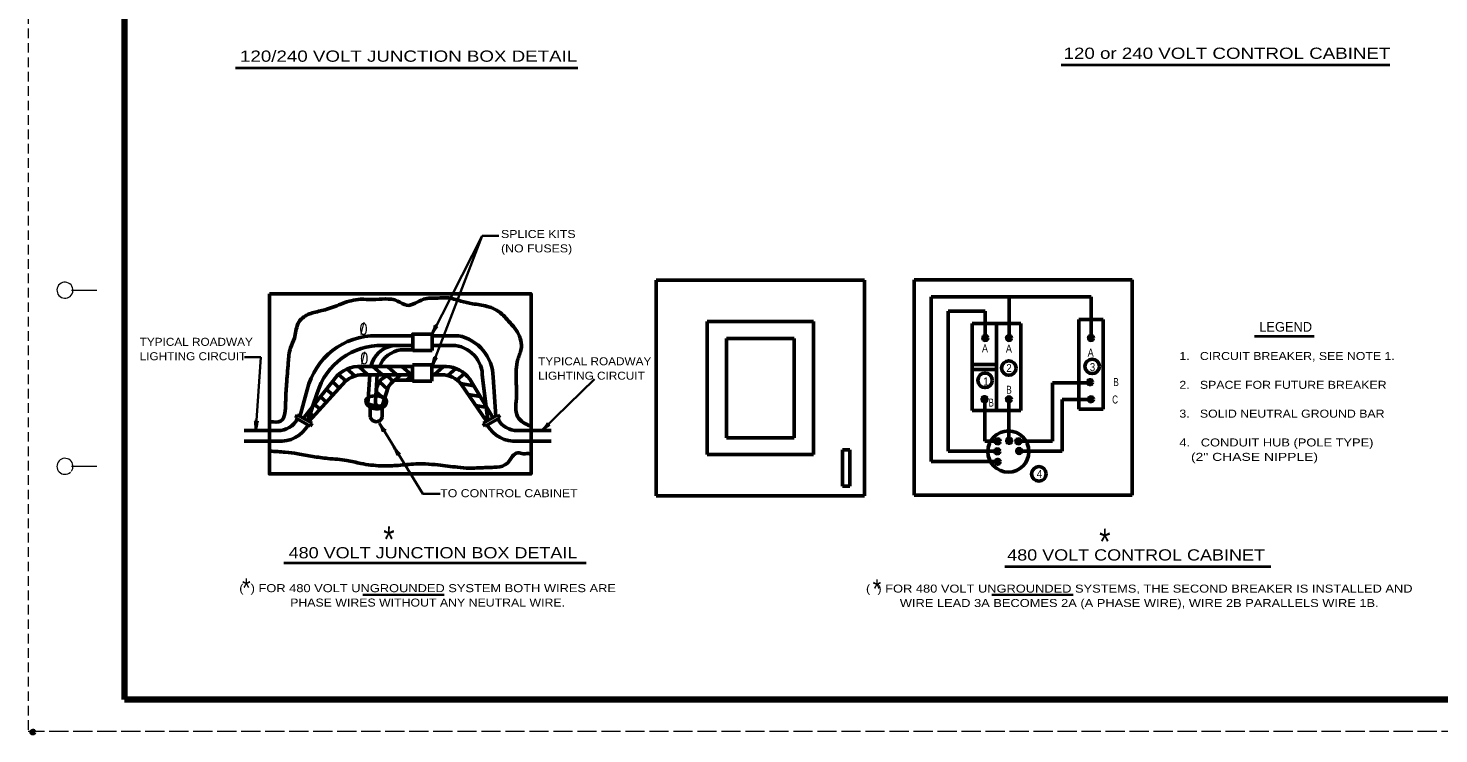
# Model space of a CAD drawing. Extents: x -1 to 679, y -1 to 440.
# Drawn here: x -1.1 to 439.6, y -1 to 219.3 of the extents above; entities that cross this region are included whole.
import ezdxf
from ezdxf.enums import TextEntityAlignment as Align

# ---------------------------------------------------------------- set-up
doc = ezdxf.new("R2010")
doc.units = 0
doc.linetypes.add('LONG_DASHED', pattern=[7.5, 6, -1.5])
doc.linetypes.add('MEDIUM_DASHED', pattern=[4.5, 3, -1.5])
doc.layers.add('1', color=7, linetype='Continuous', lineweight=53)
doc.layers.add('61', color=7, linetype='Continuous', lineweight=35)

msp = doc.modelspace()

# ---------------------------------------------------------------- hatches: boundary and pattern name
at = {"layer": '1'}
for points in [[(298.682, 122.583, 1), (297.169, 122.583, 1)], [(306.08, 122.568, 1), (304.568, 122.568, 1)], [(331.689, 122.56, 1), (330.176, 122.56, 1)], [(331.402, 108.766, 1), (329.889, 108.766, 1)], [(298.426, 103.469, 1), (296.913, 103.469, 1)], [(306.044, 103.404, 1), (304.531, 103.404, 1)], [(331.7, 103.437, 1), (330.188, 103.437, 1)], [(302.516, 90.295, 1), (301.003, 90.295, 1)], [(306.115, 90.459, 1), (304.602, 90.459, 1)], [(308.978, 90.295, 1), (307.465, 90.295, 1)], [(302.434, 87.186, 1), (300.921, 87.186, 1)], [(302.516, 83.913, 1), (301.003, 83.913, 1)], [(309.223, 87.268, 1), (307.71, 87.268, 1)], [(0.787, -0.545, 1), (-0.213, -0.545, 1)], [(0.787, -0.545, 1), (-0.213, -0.545, 1)], [(0.907, -0.519, 1), (-0.093, -0.519, 1)], [(0.909, -0.519, 1), (-0.091, -0.519, 1)], [(0.934, -0.545, 1), (-0.066, -0.545, 1)], [(0.934, -0.545, 1), (-0.066, -0.545, 1)]]:
    msp.add_hatch(color=256, dxfattribs=at).paths.add_polyline_path(points)

# ---------------------------------------------------------------- linework, layer by layer
at = {"layer": '1', "linetype": 'MEDIUM_DASHED', "lineweight": 13}
msp.add_line((-1.032, 439.694), (-1.093, -0.346), dxfattribs=at)
at = {"layer": '1', "lineweight": 40}
for p, q in [((321.613, 207.868), (424.303, 207.868)), ((63.626, 206.967), (170.602, 206.967)), ((382.012, 123.116), (400.622, 123.116)), ((78.815, 52.367), (173.2, 52.367)), ((304.007, 51.183), (387.14, 51.183))]:
    msp.add_line(p, q, dxfattribs=at)
at = {"layer": '1', "lineweight": 35}
for p, q in [((140.744, 154.494), (125.059, 123.814)), ((140.744, 154.494), (125.122, 113.85)), ((140.744, 154.494), (145.973, 154.494)), ((71.581, 116.56), (66.438, 116.564)), ((69.975, 93.743), (71.581, 116.56)), ((159.518, 93.747), (175.781, 109.732)), ((103.4, 42.355), (128.861, 42.355)), ((299.989, 42.341), (325.388, 42.341))]:
    msp.add_line(p, q, dxfattribs=at)
at = {"layer": '1'}
for p, q in [((195.111, 140.582), (195.111, 73.276)), ((195.111, 140.582), (260.149, 140.582)), ((260.149, 140.582), (260.149, 73.276)), ((275.696, 140.762), (275.696, 73.456)), ((275.696, 140.762), (343.758, 140.762)), ((343.758, 140.762), (343.758, 73.456)), ((280.989, 135.469), (280.989, 84.044)), ((280.989, 135.469), (330.935, 135.469)), ((305.31, 135.469), (305.31, 121.856)), ((330.935, 135.469), (330.935, 121.856)), ((286.283, 130.931), (286.283, 87.211)), ((286.283, 130.931), (297.894, 130.931)), ((297.894, 130.931), (297.894, 121.856)), ((327.154, 100.326), (327.154, 128.307)), ((327.154, 128.307), (334.716, 128.307)), ((334.716, 100.326), (334.716, 128.307)), ((119.059, 123.814), (125.059, 123.814)), ((119.059, 123.814), (119.059, 118.715)), ((119.059, 123.814), (119.059, 118.715)), ((119.059, 118.715), (119.059, 123.814)), ((125.059, 118.715), (125.059, 123.814)), ((210.993, 127.726), (210.993, 86.132)), ((210.993, 127.726), (244.268, 127.726)), ((244.268, 127.726), (244.268, 86.132)), ((293.846, 127.15), (293.846, 99.925)), ((293.846, 127.15), (308.971, 127.15)), ((301.408, 127.15), (301.408, 99.925)), ((308.971, 127.15), (308.971, 99.925)), ((119.059, 123.278), (107.809, 123.278)), ((109.684, 120.278), (119.059, 120.278)), ((119.059, 120.278), (109.684, 120.278)), ((125.059, 120.278), (125.059, 123.278)), ((125.059, 120.278), (131.434, 120.278)), ((217.043, 122.432), (217.043, 91.426)), ((217.043, 122.432), (238.218, 122.432)), ((238.218, 122.432), (238.218, 91.426)), ((119.268, 118.909), (115.258, 118.909)), ((119.059, 118.715), (125.059, 118.715)), ((98.163, 109.165), (95.858, 111.207)), ((100.925, 110.726), (98.467, 112.903)), ((119.059, 113.713), (101.809, 113.713)), ((105.03, 111.097), (102.064, 113.725)), ((103.309, 111.097), (119.003, 111.097)), ((103.309, 111.097), (119.003, 111.097)), ((105.04, 101.979), (105.613, 111.097)), ((109.554, 111.097), (106.601, 113.713)), ((112.956, 109.058), (111.052, 110.746)), ((114.078, 111.097), (111.125, 113.713)), ((115.356, 111.097), (113.409, 109.372)), ((118.602, 111.097), (115.649, 113.713)), ((119.074, 111.097), (117.127, 109.372)), ((119.003, 114.166), (125.003, 114.166)), ((119.003, 114.166), (119.003, 109.066)), ((125.003, 114.166), (125.003, 109.066)), ((129.559, 113.713), (125.003, 113.713)), ((128.059, 111.097), (125.003, 111.097)), ((125.686, 111.097), (128.639, 113.713)), ((129.95, 110.867), (132.456, 113.087)), ((132.859, 109.435), (135.181, 111.493)), ((140.78, 110.192), (142.49, 96.791)), ((145.019, 98.095), (144.174, 110.322)), ((293.846, 114.294), (301.408, 114.294)), ((301.408, 112.781), (293.846, 112.781)), ((86.093, 106.399), (83.75, 97.997)), ((94.094, 109.074), (84.835, 97.454)), ((98.047, 109.038), (86.553, 96.459)), ((94.115, 104.735), (92.076, 106.542)), ((96.139, 106.95), (93.948, 108.891)), ((110.188, 103.495), (107.599, 105.788)), ((111.172, 106.631), (108.62, 108.893)), ((111.358, 107.222), (109.591, 101.593)), ((113.456, 109.372), (119.003, 109.372)), ((119.003, 109.066), (125.003, 109.066)), ((138.075, 107.677), (133.981, 108.374)), ((134.116, 108.179), (142.124, 96.581)), ((136.869, 109.685), (144.072, 97.694)), ((330.643, 108.619), (318.864, 108.619)), ((318.864, 90.372), (318.864, 108.619)), ((86.282, 96.821), (89.213, 105.333)), ((90.067, 100.305), (88.332, 101.843)), ((92.091, 102.52), (90.204, 104.192)), ((108.19, 101.256), (107.345, 102.005)), ((140.112, 104.287), (136.362, 104.926)), ((142.148, 100.897), (138.744, 101.477)), ((297.76, 103.382), (297.76, 90.372)), ((305.285, 103.301), (305.285, 90.386)), ((331.052, 103.382), (321.889, 103.382)), ((321.889, 87.211), (321.889, 103.382)), ((82.97, 98.603), (82.412, 97.627)), ((82.412, 97.627), (87.01, 94.999)), ((82.97, 98.603), (87.569, 95.975)), ((82.97, 98.603), (87.569, 95.975)), ((88.043, 98.09), (86.46, 99.493)), ((105.782, 97.886), (105.782, 100.886)), ((109.532, 97.886), (109.532, 100.886)), ((141.064, 95.975), (145.663, 98.603)), ((141.064, 95.975), (145.663, 98.603)), ((146.221, 97.627), (141.622, 94.999)), ((145.663, 98.603), (146.221, 97.627)), ((308.971, 99.925), (293.846, 99.925)), ((327.154, 100.326), (334.716, 100.326)), ((76.836, 93.688), (66.336, 93.688)), ((87.569, 95.975), (87.01, 94.999)), ((141.064, 95.975), (141.622, 94.999)), ((151.796, 93.688), (162.296, 93.688)), ((76.836, 90.313), (66.336, 90.313)), ((151.796, 90.313), (162.296, 90.313)), ((217.043, 91.426), (238.218, 91.426)), ((297.76, 90.372), (301.359, 90.372)), ((308.312, 90.372), (318.864, 90.372)), ((210.993, 86.132), (244.268, 86.132)), ((253.343, 87.645), (253.343, 76.301)), ((253.343, 87.645), (255.611, 87.645)), ((255.611, 87.645), (255.611, 76.301)), ((280.989, 84.044), (301.359, 84.044)), ((286.283, 87.211), (301.359, 87.211)), ((308.312, 87.211), (321.889, 87.211)), ((253.343, 76.301), (255.611, 76.301)), ((195.111, 73.276), (260.149, 73.276)), ((275.696, 73.456), (343.758, 73.456))]:
    msp.add_line(p, q, dxfattribs=at)
msp.add_lwpolyline([(74.272, 136.366), (156.023, 136.366), (156.023, 80.116), (74.272, 80.116)], close=True, dxfattribs=at)
for points in [[(119.059, 118.715), (119.059, 123.814), (119.059, 118.715)], [(109.684, 120.278), (119.059, 120.278), (119.059, 118.715)], [(133.309, 123.278), (125.059, 123.278), (125.059, 120.278)], [(101.809, 113.713), (119.059, 113.713), (105.916, 113.713)], [(107.956, 111.097), (107.296, 101.266), (105.04, 101.979)]]:
    msp.add_lwpolyline(points, dxfattribs=at)
at = {"layer": '1', "lineweight": 35}
msp.add_lwpolyline([(108.607, 95.941), (122.181, 73.932), (127.628, 73.932)], dxfattribs=at)
at = {"layer": '1'}
for centre, radius in [((297.926, 122.583), 0.756), ((305.324, 122.568), 0.756), ((330.932, 122.56), 0.756), ((305.256, 113.19), 2.269), ((331.298, 113.712), 2.269), ((297.822, 109.345), 2.269), ((330.645, 108.766), 0.756), ((297.669, 103.469), 0.756), ((305.288, 103.404), 0.756), ((330.944, 103.437), 0.756), ((305.108, 87.11), 6.428), ((301.759, 90.295), 0.756), ((305.358, 90.459), 0.756), ((308.221, 90.295), 0.756), ((301.677, 87.186), 0.756), ((301.759, 83.913), 0.756), ((308.467, 87.268), 0.756), ((314.651, 80.125), 2.269), ((0.287, -0.545), 0.5), ((0.287, -0.545), 0.5), ((0.407, -0.519), 0.5), ((0.409, -0.519), 0.5), ((0.434, -0.545), 0.5), ((0.434, -0.545), 0.5)]:
    msp.add_circle(centre, radius, dxfattribs=at)
for centre, radius, start, end in [((107.465, 101.312), 21.969, 89.10191, 166.6119), ((109.243, 99.389), 20.894, 88.79119, 163.46999), ((114.424, 111.616), 8.762, 99.33482, 166.15506), ((131.134, 110.627), 9.655, 357.41613, 88.21923), ((130.68, 110.039), 13.497, 1.20125, 78.7649), ((116.679, 110.263), 8.762, 99.33482, 156.80988), ((102.391, 104.01), 9.72, 93.43035, 148.6064), ((103.287, 103.397), 7.7, 89.83779, 132.89463), ((112.786, 105.947), 5.102, 84.95544, 184.27235), ((128.081, 103.397), 7.7, 38.39054, 90.16221), ((128.978, 104.01), 9.72, 35.7187, 86.56965), ((115.947, 104.841), 5.17, 118.7963, 152.57809), ((77.021, 100.583), 6.897, 268.46061, 331.14947), ((107.657, 98.375), 1.938, 194.60928, 345.39072), ((151.611, 100.583), 6.897, 208.85053, 271.53939), ((77.574, 100.417), 10.131, 265.82241, 330.12509), ((151.058, 100.417), 10.131, 209.87491, 274.17759)]:
    msp.add_arc(centre, radius, start, end, dxfattribs=at)
at = {"layer": '1', "lineweight": 40}
for centre, major_axis, ratio, start_param, end_param in [((125.31, 124.911), (-0.674, -1.661), 0.122415, 0.8963533, 3.1415927), ((125.758, 124.715), (-0.956, -1.484), 0.07063, 3.1407148, 5.41811), ((125.255, 114.968), (-0.495, -1.723), 0.122415, 0.8963533, 3.1415927), ((125.721, 114.82), (0.794, 1.576), 0.07063, 6.2823074, 8.5597026), ((69.776, 94.851), (0.03, -1.792), 0.122415, 0.8963533, 3.1415927), ((70.265, 94.846), (0.299, 1.74), 0.07063, 6.2823074, 8.5597026), ((109.015, 94.877), (0.772, -1.587), 0.07063, 6.2823074, 8.5597026), ((109.015, 94.877), (0.772, -1.587), 0.07063, 6.2823074, 8.5597026), ((109.415, 95.158), (-1.07, 1.438), 0.122415, 0.8963533, 3.1415927), ((109.415, 95.158), (-1.07, 1.438), 0.122415, 0.8963533, 3.1415927), ((160.103, 94.709), (-1.164, -1.363), 0.122415, 0.8963533, 3.1415927), ((160.466, 94.382), (1.376, 1.106), 0.07063, 6.2823074, 8.5597026), ((113.583, 87.47), (0.772, -1.587), 0.07063, 6.2823074, 8.5597026), ((113.983, 87.752), (-1.07, 1.438), 0.122415, 0.8963533, 3.1415927)]:
    msp.add_ellipse(centre, major_axis=major_axis, ratio=ratio, start_param=start_param, end_param=end_param, dxfattribs=at)
at = {"layer": '1'}
msp.add_ellipse((107.635, 102.881), major_axis=(3.232, -0.12), ratio=0.757256, start_param=3.1415927, end_param=6.2831853, dxfattribs=at)
msp.add_ellipse((107.635, 102.881), major_axis=(3.232, -0.12), ratio=0.505045, dxfattribs=at)
for points in [[(74.545, 96.436), (77.76, 96.62), (79.321, 102.409), (79.597, 108.106), (80.148, 114.905), (80.883, 119.5), (82.077, 122.532), (83.179, 126.943), (84.649, 128.872), (88.139, 130.526), (92.181, 131.537), (97.141, 133.375), (99.805, 134.202), (102.745, 134.661), (106.511, 134.569), (114.319, 134.11), (117.182, 132.782), (122.402, 134.661), (126.903, 135.029), (129.751, 135.121), (134.068, 134.11), (137.742, 133.283), (142.243, 132.456), (145.55, 131.078), (148.949, 127.862), (151.337, 125.013), (152.991, 119.684), (151.888, 115.916), (151.337, 109.392), (151.429, 107.003), (151.429, 103.695), (151.245, 100.112), (152.164, 97.447), (154.093, 95.885), (156.206, 94.966)], [(74.453, 87.248), (79.229, 86.88), (83.087, 86.421), (87.772, 85.594), (92.549, 84.95), (98.427, 84.307), (102.837, 83.388), (109.083, 82.653), (113.859, 82.745), (119.187, 83.205), (126.903, 82.929), (133.058, 82.194), (136.824, 81.918), (139.855, 82.01), (144.448, 82.194), (147.847, 82.929), (149.408, 84.399), (150.143, 85.594), (151.888, 86.696), (153.542, 86.421), (155.838, 86.329), (156.074, 86.219)]]:
    msp.add_spline(points, degree=3, dxfattribs=at)
at = {"layer": '61', "lineweight": 13}
for p, q in [((12.387, 137.514), (20.387, 137.514)), ((12.407, 82.494), (20.387, 82.494))]:
    msp.add_line(p, q, dxfattribs=at)
at = {"layer": '61', "lineweight": 158}
msp.add_line((668.028, 9.654), (28.967, 9.674), dxfattribs=at)
at = {"layer": '61', "linetype": 'LONG_DASHED', "lineweight": 13}
msp.add_line((678.967, -0.326), (-1.093, -0.346), dxfattribs=at)
at = {"layer": '61', "lineweight": 158}
msp.add_lwpolyline([(668.007, 429.694), (28.967, 429.694), (28.967, 9.674)], dxfattribs=at)
at = {"layer": '61', "lineweight": 13}
for centre, start, end in [((10.385, 137.495), 322.67175, 321.71615), ((10.385, 82.495), 323.13009, 312.31439)]:
    msp.add_arc(centre, 2.5, start, end, dxfattribs=at)

# ---------------------------------------------------------------- texts
at = {"layer": '1'}
for s, height, width, p in [('120/240 VOLT JUNCTION BOX DETAIL', 3.5, 1.25, (65.078, 208.856)), ('120 or 240 VOLT CONTROL CABINET', 3.5, 1.25, (322.354, 209.757)), ('SPLICE KITS', 2.5, 1.15, (146.622, 153.806)), ('(NO FUSES)', 2.5, 1.15, (146.622, 149.306)), ('0', 3.75, 0.9, (102.404, 123.504)), ('TYPICAL ROADWAY', 2.5, 1.1, (33.73, 120.123)), ('A', 2.5, 0.85, (296.856, 118.066)), ('A', 2.5, 0.85, (304.327, 118.003)), ('A', 2.5, 0.85, (329.881, 116.744)), ('LIGHTING CIRCUIT', 2.5, 1.1, (33.73, 115.623)), ('0', 3.75, 0.9, (102.638, 114.348)), ('TYPICAL ROADWAY', 2.5, 1.1, (158.222, 114.044)), ('3', 2.5, 0.9, (330.556, 112.239)), ('1.   CIRCUIT BREAKER, SEE NOTE 1.', 2.5, 1.15, (358.536, 115.694)), ('LIGHTING CIRCUIT', 2.5, 1.1, (158.222, 109.544)), ('2', 2.5, 0.9, (304.478, 111.953)), ('B', 2.5, 0.75, (304.48, 105.14)), ('B', 2.5, 0.75, (337.932, 107.563)), ('2.   SPACE FOR FUTURE BREAKER', 2.5, 1.15, (358.536, 106.694)), ('B', 2.5, 0.75, (298.916, 101.145)), ('C', 2.5, 0.75, (337.554, 102.119)), ('3.   SOLID NEUTRAL GROUND BAR', 2.5, 1.15, (358.536, 97.694)), ('4.   CONDUIT HUB (POLE TYPE)', 2.5, 1.2, (358.536, 88.694)), ('   (2" CHASE NIPPLE)', 2.5, 1.3, (358.536, 84.194)), ('4', 2.5, 0.95, (313.965, 78.876)), ('TO CONTROL CABINET', 2.5, 1.15, (127.628, 72.842)), ('*', 8, 0.85, (109.822, 55.71)), ('*', 8, 0.85, (333.48, 54.972)), ('480 VOLT JUNCTION BOX DETAIL', 3.5, 1.2, (80.268, 53.748)), ('480 VOLT CONTROL CABINET', 3.5, 1.2, (304.748, 53.072)), ('*', 6, 0.85, (65.734, 41.512)), ('*', 6, 0.85, (262.709, 41.246))]:
    msp.add_text(s, height=height, dxfattribs=dict(at, width=width)).set_placement(p)
for s, height, p in [('/', 3.75, (102.622, 123.613)), ('LEGEND', 3, (383.491, 124.561)), ('/', 3.75, (102.855, 114.348)), ('1', 2.5, (297.226, 107.764))]:
    msp.add_text(s, height=height, dxfattribs=at).set_placement(p)
for s, width, p in [('(  ) FOR 480 VOLT UNGROUNDED SYSTEM BOTH WIRES ARE', 1.2, (123.681, 43.186)), ('(  ) FOR 480 VOLT UNGROUNDED SYSTEMS, THE SECOND BREAKER IS INSTALLED AND', 1.2, (346.001, 43.049)), ('PHASE WIRES WITHOUT ANY NEUTRAL WIRE.', 1.15, (123.681, 38.686)), ('WIRE LEAD 3A BECOMES 2A (A PHASE WIRE), WIRE 2B PARALLELS WIRE 1B.', 1.2, (346.001, 38.549))]:
    msp.add_text(s, height=2.5, dxfattribs=dict(at, width=width)).set_placement(p, align=Align.CENTER)

doc.saveas('drawing.dxf')
